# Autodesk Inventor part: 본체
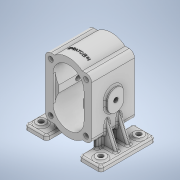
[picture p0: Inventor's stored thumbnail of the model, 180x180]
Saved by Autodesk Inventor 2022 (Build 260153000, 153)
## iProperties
Created: 2023-06
Part Number: 본체
Material: 일반
Document SubType Name: Modeling
Designer: PC-01
Density: 1 g/cm^3
Appearance: 기본값
Author: PC-01
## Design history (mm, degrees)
sketch "스케치1"
  geometry: L1 (-61.534, 0)-(63.223, 0) reference; L2 (0, -90.68)-(0, 96.081) reference; L3 (-42.5, 55)-(-42.5, -55); L4 (-42.5, -55)-(42.5, -55); L5 (42.5, -55)-(42.5, 55); L6 (42.5, 55)-(-42.5, 55); L7 (-22.5, 6.507)-(-22.5, -6.507); L8 (22.5, 6.507)-(22.5, -6.507); L9 (-28.5, 24)-(-28.5, -24); L10 (28.5, 24)-(28.5, -24); A1 r 28.5 centre (0, 24) between (22.5, 6.507) and (-22.5, 6.507); A2 r 28.5 centre (0, -24) between (-22.5, -6.507) and (22.5, -6.507); A3 r 40 centre (0, 24) between (23.723, -8.206) and (-32, 0); A4 r 40 centre (0, -24) between (-32, 0) and (32, 0); 5 further points
  constraints: 16 end point, 14 point on circle, 4 centre point, 3 parallel, 3 vertical, 2 coincident, 2 perpendicular, 2 point on line, 2 tangent, 1 symmetric about line, 3 other
  dimensions: "d0" = 110 distance between parallel lines of L4 L6; "d1" = 85 distance of L5.end L3.start; "d2" = 48 distance of A2.centre A1.centre; "d3" = 57 diameter of A1; "d4" = 80 diameter of A3; "d5" = 80 diameter of A4; "d6" = 57 diameter of A2; "d7" = 45 distance between parallel lines of L8 L7
extrude "돌출1" new body sketch "스케치1" stored distance "d8" = 79; taper "d9" = 0 deg
extrude "돌출2" join sketch "스케치1" stored distance "d10" = 70; taper "d11" = 0 deg
fillet "모깎기1" dims "d12" = 10
node "작업 평면1"
sketch "스케치2"
  geometry: L1 (70, -50)-(30, -50); L2 (30, -50)-(30, 50); L3 (30, 50)-(70, 50); L4 (70, 50)-(70, -50); L5 (-30, -50)-(-70, -50); L6 (-70, -50)-(-70, 50); L7 (-70, 50)-(-30, 50); L8 (-30, 50)-(-30, -50); L9 (102.685, 0)-(-119.489, 0) reference; L10 (0, -59.722)-(0, 81.834) reference; 1 further point
  constraints: 16 end point, 4 parallel, 2 horizontal, 2 perpendicular, 2 point on line, 3 other
  dimensions: "d14" = 40 distance of L1.start L1.end; "d15" = 100 distance of L3.end L1.start; "d16" = 140 distance of L5.end L1.start
extrude "돌출3" join sketch "스케치2" distance "d17" = 9; taper "d18" = 0 deg
sketch "스케치3"
  geometry: L1 (-30, -80)-(-30, -71) reference; L2 (-30, -71)-(-38, -71); L3 (-38, -71)-(-38, -31.856); L4 (-38, -31.856)-(-30, -31.856); L5 (-30, -31.856)-(-30, -71); L6 (70, -71)-(30, -71) reference; L7 (30, -71)-(38, -71); L8 (38, -71)-(38, -35.229); L9 (38, -35.229)-(30, -35.229); L10 (30, -35.229)-(30, -71); 2 further points
  constraints: 16 end point, 4 parallel, 2 horizontal, 2 perpendicular
  dimensions: "d19" = 8 distance of L3.end L4.end; "d20" = 8 distance of L8.end L9.end; "d21" = 39.14441 distance of L2.end L3.end; "d22" = 35.77147 distance of L7.end L8.end
extrude "돌출4" join sketch "스케치3" stored distance "d23" = 50; taper "d24" = 0 deg
sketch "스케치4"
  geometry: L1 (-100.487, 0)-(98.414, 0) reference; L2 (0, 72.936)-(0, -71.25) reference; C1 r 9 at (-55, 35); C2 r 9 at (-55, -35); C3 r 9 at (55, 35); C4 r 9 at (55, -35); 1 further point
  constraints: 4 centre point, 4 symmetric about line
  dimensions: "d25" = 18 diameter of C1; "d26" = 70 distance of C2.centre C1.centre; "d27" = 110 distance of C3.centre C1.centre; "d28" = 18 diameter of C3; "d29" = 18 diameter of C2; "d30" = 18 diameter of C4
extrude "돌출5" join sketch "스케치4" distance "d31" = 3; taper "d32" = 0 deg
fillet "모깎기2" dims "d33" = 5
fillet "모깎기3" dims "d34" = 3
fillet "모깎기4" dims "d35" = 3
sketch "스케치5"
  geometry: C1 r 9 at (0, 0) reference; C2 r 9 at (0, -70) reference; C3 r 9 at (-110, -70) reference; C4 r 9 at (-110, 0) reference; 5 further points
  constraints: 4 coincident
hole "구멍1" sketch "스케치5" at (0, 0), (0, -70), (-110, -70), (-110, 0) diameter "d36" = 9; stored, may be unused: countersink angle "d40" = 90 deg, drill point angle "d42" = 118 deg; dims "d37" = 6, "d38" = 4, "d39" = 2, "d41" = 8
node "작업 평면2"
sketch "스케치6"
  geometry: L1 (42.5, -45)-(42.5, 45) reference; L2 (42.5, -25.061)-(62, -71); L3 (70, -74)-(70, -80) reference; L4 (33, -71)-(38, -71) reference; L5 (38, -71)-(70, -71); 1 further point
  constraints: 4 end point, 2 point on line, 1 horizontal
  dimensions: "d44" = 23 deg angle of L2 L3; "d45" = 8 distance from line of L3 L2.end
feature "리브1" sketch "스케치6" dims "d46" = 1, "d47" = 7, "d48" = 0, "d49" = 0, "d50" = 1, "d51" = 1
sketch "스케치7"
  geometry: L1 (0, -108.8)-(0, 92.8) reference; L2 (-98, 0)-(98, 0) reference; C1 r 4.5 at (-32.5, 45); C2 r 4.5 at (-32.5, -45); C3 r 4.5 at (32.5, -45); C4 r 4.5 at (32.5, 45); 1 further point
  constraints: 4 centre point, 2 symmetric about line
  dimensions: "d52" = 9 diameter of C1; "d53" = 9 diameter of C4; "d54" = 9 diameter of C3; "d55" = 9 diameter of C2; "d57" = 65 distance of C3.centre C2.centre; "d58" = 90 distance of C2.centre C1.centre; "d59" = 65 distance of C4.centre C1.centre; "d60" = 45 distance from line of L2 C1.centre
extrude "돌출6" cut sketch "스케치7" distance "d61" = 79; taper "d62" = 0 deg
fillet "모깎기5" dims "d63" = 3
sketch "스케치8"
  geometry: L1 (-39.5, 65)-(-39.5, 25); L2 (-54.5, 50)-(-54.5, 40); L3 (-24.5, 40)-(-24.5, 50); L4 (-84.5, -35)-(5.5, -35) reference; L5 (-79, 0)-(-79, 90) reference; A1 r 15 centre (-39.5, 50) between (-24.5, 50) and (-54.5, 50); A2 r 15 centre (-39.5, 40) between (-54.5, 40) and (-24.5, 40); 2 further points
  constraints: 8 end point, 6 point on circle, 4 tangent, 2 centre point, 2 point on line, 1 midpoint, 1 parallel, 1 vertical
  dimensions: "d64" = 80 distance from line of L4 point (-39.5, 45); "d65" = 39.5 distance from line of L5 point (-39.5, 45); "d66" = 10 distance of A2.centre A1.centre; "d67" = 30 distance between parallel lines of L3 L2
extrude "돌출7" join sketch "스케치8" distance "d68" = 5; taper "d69" = 0 deg
sketch "스케치9"
  geometry: 1 further point
hole "구멍2" sketch "스케치9" at (-39.5, 45) diameter "d70" = 8.376; stored, may be unused: countersink angle "d74" = 82 deg, drill point angle "d76" = 118 deg; dims "d71" = 12.5, "d72" = 3.023, "d73" = 4.775, "d75" = 8
fillet "모깎기6" dims "d77" = 3
node "작업 평면3"
sketch "스케치10" dims "d10" = 70, "d11" = 0
  geometry: L1 (98, 0)-(-98, 0) reference; L2 (0, -70)-(0, 70) reference; 2 further points
  constraints: 1 point on line, 1 other
  dimensions: "d79" = 20 distance from line of L1 point (0, 20)
feature "엠보싱1" sketch "스케치10" dims "d0" = 110, "d1" = 85, "d2" = 48, "d3" = 57, "d4" = 80, "d5" = 80, "d6" = 57, "d7" = 45, "d80" = 0.5, "d81" = 0
fillet "모깎기7" dims "d82" = 3
node "솔리드1"
mirror "미러1"
mirror "미러2"
mirror "미러3"
mirror "미러4"
feature "A9D066F2-1C7D-4E18-AEED-F7BC21143FA4" dims "d70" = 8.376, "d71" = 12.5, "d72" = 3.023, "d73" = 4.775, "d74" = 82 deg, "d75" = 8, "d76" = 118 deg
other parameters: "d43" = 11
